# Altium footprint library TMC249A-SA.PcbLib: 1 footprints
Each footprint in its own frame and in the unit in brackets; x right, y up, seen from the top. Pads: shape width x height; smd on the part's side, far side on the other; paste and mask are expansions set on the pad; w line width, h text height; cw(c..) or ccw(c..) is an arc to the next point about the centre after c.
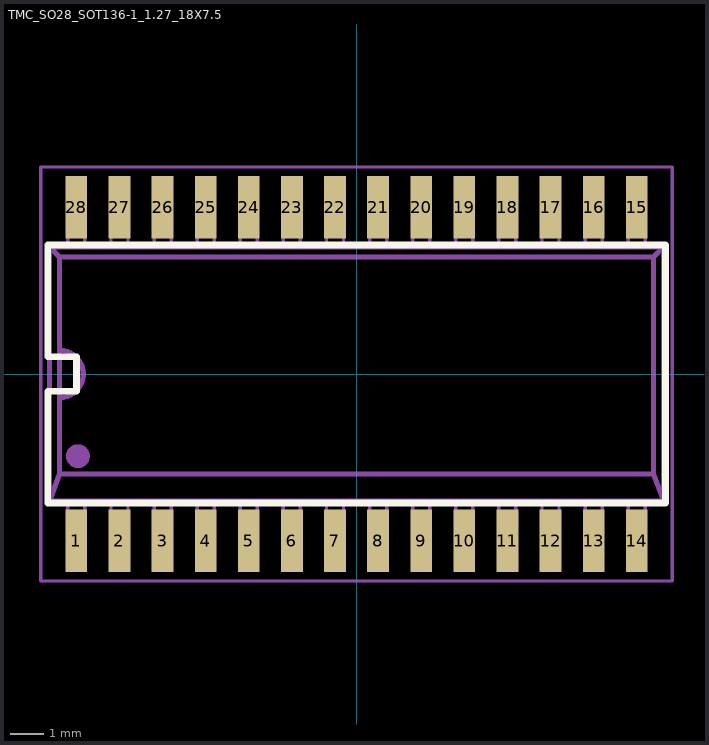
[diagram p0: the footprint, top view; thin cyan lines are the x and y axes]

## TMC_SO28_SOT136-1_1.27_18X7.5 [mm]
pads (28):
  rect 0.64x1.83 smd: 1(-8.255,-4.912) 2(-6.985,-4.912) 3(-5.715,-4.912) 4(-4.445,-4.912) 5(-3.175,-4.912) 6(-1.905,-4.912) 7(-0.635,-4.912) 8(0.635,-4.912) 9(1.905,-4.912) 10(3.175,-4.912) 11(4.445,-4.912) 12(5.715,-4.912) 13(6.985,-4.912) 14(8.255,-4.912) 15(8.255,4.912) 16(6.985,4.912) 17(5.715,4.912) 18(4.445,4.912) 19(3.175,4.912) 20(1.905,4.912) 21(0.635,4.912) 22(-0.635,4.913) 23(-1.905,4.912) 24(-3.175,4.912) 25(-4.445,4.912) 26(-5.715,4.912) 27(-6.985,4.912) 28(-8.255,4.912)
L26-Silk Screen Top (Multiple PADS layers...):
  lines w0.2: -9.1,-3.8 9.1,-3.8 9.1,3.8 -9.1,3.8 -9.1,0.508 -8.255,0.508 -8.255,-0.508 -9.1,-0.508 -9.1,-3.8
L13:
  circle w0.5: c-8.21,-2.42 r0.1
  lines w0.1: -8.505,-3.75 -8.505,-5.3 -8.005,-5.3 -8.005,-3.75 ; -8.505,3.75 -8.505,5.3 -8.005,5.3 -8.005,3.75 ; -7.235,-3.75 -7.235,-5.3 -6.735,-5.3 -6.735,-3.75 ; -7.235,3.75 -7.235,5.3 -6.735,5.3 -6.735,3.75 ; -5.965,-3.75 -5.965,-5.3 -5.465,-5.3 -5.465,-3.75 ; -5.965,3.75 -5.965,5.3 -5.465,5.3 -5.465,3.75 ; -4.695,-3.75 -4.695,-5.3 -4.195,-5.3 -4.195,-3.75 ; -4.695,3.75 -4.695,5.3 -4.195,5.3 -4.195,3.75 ; -3.425,-3.75 -3.425,-5.3 -2.925,-5.3 -2.925,-3.75 ; -3.425,3.75 -3.425,5.3 -2.925,5.3 -2.925,3.75 ; -2.155,-3.75 -2.155,-5.3 -1.655,-5.3 -1.655,-3.75 ; -2.155,3.75 -2.155,5.3 -1.655,5.3 -1.655,3.75 ; -0.885,-3.75 -0.885,-5.3 -0.385,-5.3 -0.385,-3.75 ; -0.885,3.75 -0.885,5.3 -0.385,5.3 -0.385,3.75 ; 0.385,-3.75 0.385,-5.3 0.885,-5.3 0.885,-3.75 ; 0.385,3.75 0.385,5.3 0.885,5.3 0.885,3.75 ; 1.655,-3.75 1.655,-5.3 2.155,-5.3 2.155,-3.75 ; 1.655,3.75 1.655,5.3 2.155,5.3 2.155,3.75 ; 2.925,-3.75 2.925,-5.3 3.425,-5.3 3.425,-3.75 ; 2.925,3.75 2.925,5.3 3.425,5.3 3.425,3.75 ; 4.195,-3.75 4.195,-5.3 4.695,-5.3 4.695,-3.75 ; 4.195,3.75 4.195,5.3 4.695,5.3 4.695,3.75 ; 5.465,-3.75 5.465,-5.3 5.965,-5.3 5.965,-3.75 ; 5.465,3.75 5.465,5.3 5.965,5.3 5.965,3.75 ; 6.735,-3.75 6.735,-5.3 7.235,-5.3 7.235,-3.75 ; 6.735,3.75 6.735,5.3 7.235,5.3 7.235,3.75 ; 8.005,-3.75 8.005,-5.3 8.505,-5.3 8.505,-3.75 ; 8.005,3.75 8.005,5.3 8.505,5.3 8.505,3.75
  lines w0.15: -9.05,-3.75 -8.75,-2.95 ; -9.05,-3.75 -9.05,3.75 ; -9.05,-3.75 9.05,-3.75 ; -9.05,3.75 -8.75,3.45 ; -9.05,3.75 9.05,3.75 ; -8.75,-2.95 -8.75,-0.7 ; -8.75,-2.95 8.75,-2.95 ; -8.75,-0.7 ccw(c-8.75,0) -8.75,0.7 ; -8.75,-0.7 -8.75,0.7 ; -8.75,0.7 -8.75,3.45 ; -8.75,3.45 8.75,3.45 ; 8.75,-2.95 9.05,-3.75 ; 8.75,-2.95 8.75,3.45 ; 8.75,3.45 9.05,3.75 ; 9.05,-3.75 9.05,3.75
L15 (Multiple PADS layers...):
  lines w0.1: -9.3,-6.1 -9.3,6.1 9.3,6.1 9.3,-6.1 -9.3,-6.1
